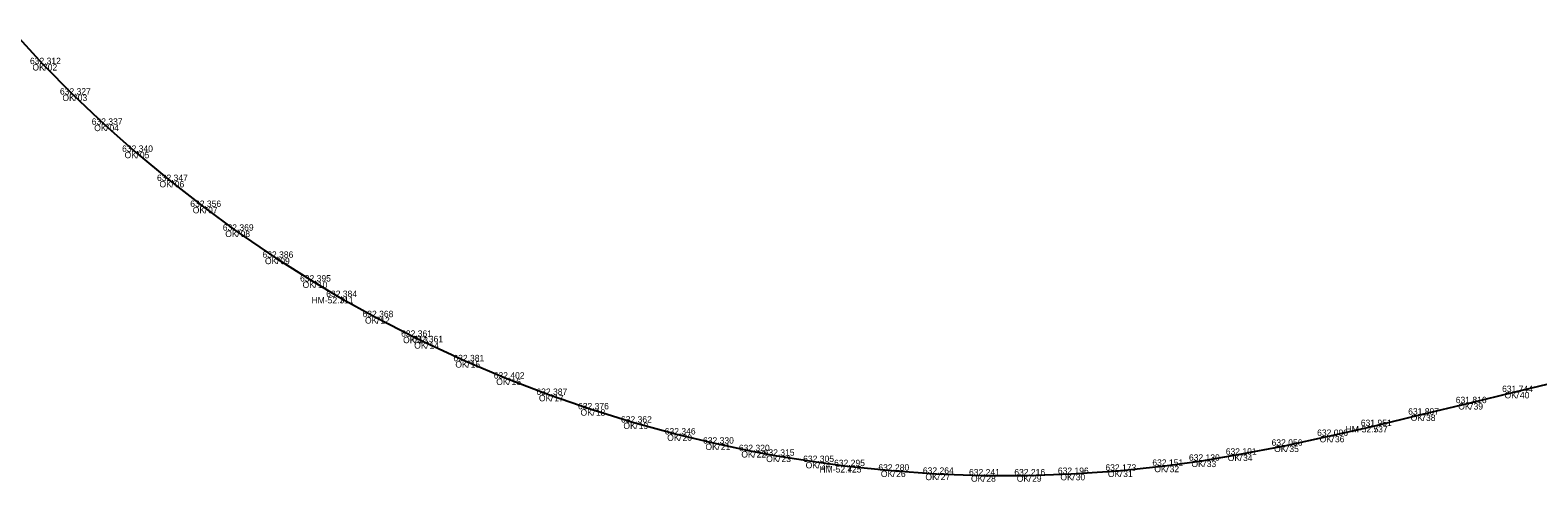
# Model space of a CAD drawing. Extents: x -631472 to -620808, y -1122356 to -1115125.
# Drawn here: x -627753.5 to -627470.2, y -1117415.3 to -1117330.3 of the extents above; entities that cross this region are included whole.
import ezdxf

# ---------------------------------------------------------------- set-up
doc = ezdxf.new("R2010")
doc.units = 0
for name, color, linetype in [('Vrstva 1', 7, 'Continuous'), ('Vrstva 60', 7, 'Continuous'), ('Vrstva 61', 7, 'Continuous'), ('Vrstva 62', 7, 'Continuous')]:
    doc.layers.add(name, color=color, linetype=linetype)

msp = doc.modelspace()

# ---------------------------------------------------------------- linework, layer by layer
at = {"layer": 'Vrstva 1'}
msp.add_lwpolyline([(-627757, -1117330.33), (-627751.12, -1117336.72), (-627745.48, -1117342.44), (-627739.51, -1117348.12), (-627733.8, -1117353.21), (-627727.24, -1117358.69), (-627720.98, -1117363.57), (-627714.88, -1117368.04), (-627707.42, -1117373.13), (-627700.35, -1117377.6), (-627695.44, -1117380.51), (-627688.62, -1117384.3), (-627681.45, -1117387.99), (-627679.37, -1117389.01), (-627671.64, -1117392.59), (-627663.96, -1117395.85), (-627655.94, -1117398.92), (-627648.11, -1117401.63), (-627640.05, -1117404.12), (-627631.82, -1117406.36), (-627624.63, -1117408.08), (-627617.9, -1117409.49), (-627613.23, -1117410.35), (-627605.81, -1117411.53), (-627599.99, -1117412.31), (-627591.68, -1117413.16), (-627583.31, -1117413.75), (-627574.73, -1117414.05), (-627566.13, -1117414.05), (-627557.94, -1117413.78), (-627549.01, -1117413.17), (-627540.29, -1117412.25), (-627533.31, -1117411.29), (-627526.48, -1117410.15), (-627517.78, -1117408.47), (-627509.22, -1117406.63), (-627501.1, -1117404.77), (-627492.1, -1117402.62), (-627483.17, -1117400.47), (-627474.46, -1117398.37), (-627466.85, -1117396.54)], dxfattribs=at)
at = {"layer": 'Vrstva 60'}
for p, q in [((-627751.12, -1117336.72), (-627751.12, -1117336.72)), ((-627745.48, -1117342.44), (-627745.48, -1117342.44)), ((-627739.51, -1117348.12), (-627739.51, -1117348.12)), ((-627733.8, -1117353.21), (-627733.8, -1117353.21)), ((-627727.24, -1117358.69), (-627727.24, -1117358.69)), ((-627720.98, -1117363.57), (-627720.98, -1117363.57)), ((-627714.88, -1117368.04), (-627714.88, -1117368.04)), ((-627707.42, -1117373.13), (-627707.42, -1117373.13)), ((-627700.35, -1117377.6), (-627700.35, -1117377.6)), ((-627695.44, -1117380.51), (-627695.44, -1117380.51)), ((-627688.62, -1117384.3), (-627688.62, -1117384.3)), ((-627681.45, -1117387.99), (-627681.45, -1117387.99)), ((-627679.37, -1117389.01), (-627679.37, -1117389.01)), ((-627671.64, -1117392.59), (-627671.64, -1117392.59)), ((-627663.96, -1117395.85), (-627663.96, -1117395.85)), ((-627474.46, -1117398.37), (-627474.46, -1117398.37)), ((-627655.94, -1117398.92), (-627655.94, -1117398.92)), ((-627483.17, -1117400.47), (-627483.17, -1117400.47)), ((-627648.11, -1117401.63), (-627648.11, -1117401.63)), ((-627640.05, -1117404.12), (-627640.05, -1117404.12)), ((-627492.1, -1117402.62), (-627492.1, -1117402.62)), ((-627631.82, -1117406.36), (-627631.82, -1117406.36)), ((-627509.22, -1117406.63), (-627509.22, -1117406.63)), ((-627501.1, -1117404.77), (-627501.1, -1117404.77)), ((-627624.63, -1117408.08), (-627624.63, -1117408.08)), ((-627617.9, -1117409.49), (-627617.9, -1117409.49)), ((-627517.78, -1117408.47), (-627517.78, -1117408.47)), ((-627613.23, -1117410.35), (-627613.23, -1117410.35)), ((-627605.81, -1117411.53), (-627605.81, -1117411.53)), ((-627599.99, -1117412.31), (-627599.99, -1117412.31)), ((-627540.29, -1117412.25), (-627540.29, -1117412.25)), ((-627533.31, -1117411.29), (-627533.31, -1117411.29)), ((-627526.48, -1117410.15), (-627526.48, -1117410.15)), ((-627591.68, -1117413.16), (-627591.68, -1117413.16)), ((-627583.31, -1117413.75), (-627583.31, -1117413.75)), ((-627574.73, -1117414.05), (-627574.73, -1117414.05)), ((-627566.13, -1117414.05), (-627566.13, -1117414.05)), ((-627557.94, -1117413.78), (-627557.94, -1117413.78)), ((-627549.01, -1117413.17), (-627549.01, -1117413.17))]:
    msp.add_line(p, q, dxfattribs=at)

# ---------------------------------------------------------------- texts
for s, p in [('702', (-627751.12, -1117337.92)), ('703', (-627745.48, -1117343.64)), ('704', (-627739.51, -1117349.32)), ('705', (-627733.8, -1117354.41)), ('706', (-627727.24, -1117359.89)), ('707', (-627720.98, -1117364.77)), ('708', (-627714.88, -1117369.24)), ('709', (-627707.42, -1117374.33)), ('710', (-627700.35, -1117378.8)), ('711', (-627695.44, -1117381.71)), ('712', (-627688.62, -1117385.5)), ('713', (-627681.45, -1117389.19)), ('714', (-627679.37, -1117390.21)), ('715', (-627671.64, -1117393.79)), ('716', (-627663.96, -1117397.05)), ('740', (-627474.46, -1117399.57)), ('717', (-627655.94, -1117400.12)), ('739', (-627483.17, -1117401.67)), ('718', (-627648.11, -1117402.83)), ('719', (-627640.05, -1117405.32)), ('738', (-627492.1, -1117403.82)), ('720', (-627631.82, -1117407.56)), ('736', (-627509.22, -1117407.83)), ('737', (-627501.1, -1117405.97)), ('721', (-627624.63, -1117409.28)), ('722', (-627617.9, -1117410.69)), ('735', (-627517.78, -1117409.67)), ('723', (-627613.23, -1117411.55)), ('724', (-627605.81, -1117412.74)), ('725', (-627599.99, -1117413.51)), ('732', (-627540.29, -1117413.45)), ('733', (-627533.31, -1117412.49)), ('734', (-627526.48, -1117411.35)), ('726', (-627591.68, -1117414.36)), ('727', (-627583.31, -1117414.95)), ('728', (-627574.73, -1117415.25)), ('729', (-627566.13, -1117415.25)), ('730', (-627557.94, -1117414.98)), ('731', (-627549.01, -1117414.37))]:
    msp.add_text(s, height=1.2, dxfattribs=at).set_placement(p)
at = {"layer": 'Vrstva 61'}
for s, p in [('632.312', (-627753.56, -1117336.72)), ('632.327', (-627747.93, -1117342.44)), ('632.337', (-627741.96, -1117348.12)), ('632.340', (-627736.25, -1117353.21)), ('632.347', (-627729.69, -1117358.69)), ('632.356', (-627723.44, -1117363.57)), ('632.369', (-627717.33, -1117368.04)), ('632.386', (-627709.87, -1117373.13)), ('632.395', (-627702.81, -1117377.6)), ('632.384', (-627697.89, -1117380.51)), ('632.368', (-627691.07, -1117384.3)), ('632.361', (-627683.81, -1117387.99)), ('632.361', (-627681.73, -1117389.01)), ('632.381', (-627673.99, -1117392.59)), ('632.402', (-627666.41, -1117395.85)), ('632.387', (-627658.39, -1117398.92)), ('631.744', (-627476.91, -1117398.37)), ('632.376', (-627650.57, -1117401.63)), ('631.897', (-627494.56, -1117402.62)), ('631.816', (-627485.62, -1117400.47)), ('632.362', (-627642.5, -1117404.12)), ('631.951', (-627503.46, -1117404.77)), ('632.346', (-627634.27, -1117406.36)), ('632.330', (-627627.08, -1117408.08)), ('632.006', (-627511.67, -1117406.63)), ('632.320', (-627620.35, -1117409.49)), ('632.315', (-627615.68, -1117410.35)), ('632.101', (-627528.84, -1117410.15)), ('632.056', (-627520.23, -1117408.47)), ('632.305', (-627608.26, -1117411.53)), ('632.295', (-627602.45, -1117412.31)), ('632.280', (-627594.13, -1117413.16)), ('632.264', (-627585.76, -1117413.75)), ('632.241', (-627577.09, -1117414.05)), ('632.216', (-627568.58, -1117414.05)), ('632.196', (-627560.39, -1117413.78)), ('632.173', (-627551.46, -1117413.17)), ('632.151', (-627542.64, -1117412.25)), ('632.130', (-627535.76, -1117411.29))]:
    msp.add_text(s, height=1.2, dxfattribs=at).set_placement(p)
at = {"layer": 'Vrstva 62'}
for s, p in [('OK', (-627753.1, -1117337.92)), ('OK', (-627747.46, -1117343.64)), ('OK', (-627741.49, -1117349.32)), ('OK', (-627735.78, -1117354.41)), ('OK', (-627729.22, -1117359.89)), ('OK', (-627722.97, -1117364.77)), ('OK', (-627716.86, -1117369.24)), ('OK', (-627709.4, -1117374.33)), ('OK', (-627702.33, -1117378.8)), ('HM-52.3', (-627700.65, -1117381.71)), ('OK', (-627690.6, -1117385.5)), ('OK', (-627683.44, -1117389.19)), ('OK', (-627681.35, -1117390.21)), ('OK', (-627673.62, -1117393.79)), ('OK', (-627665.94, -1117397.05)), ('OK', (-627476.45, -1117399.57)), ('OK', (-627657.92, -1117400.12)), ('OK', (-627485.15, -1117401.67)), ('OK', (-627650.1, -1117402.83)), ('OK', (-627642.04, -1117405.32)), ('OK', (-627494.09, -1117403.82)), ('OK', (-627633.81, -1117407.56)), ('OK', (-627511.2, -1117407.83)), ('HM-52.5', (-627506.32, -1117405.97)), ('OK', (-627626.62, -1117409.28)), ('OK', (-627619.88, -1117410.69)), ('OK', (-627519.76, -1117409.67)), ('OK', (-627615.21, -1117411.55)), ('OK', (-627607.79, -1117412.74)), ('HM-52.4', (-627605.19, -1117413.51)), ('OK', (-627542.27, -1117413.45)), ('OK', (-627535.29, -1117412.49)), ('OK', (-627528.47, -1117411.35)), ('OK', (-627593.66, -1117414.36)), ('OK', (-627585.29, -1117414.95)), ('OK', (-627576.72, -1117415.25)), ('OK', (-627568.11, -1117415.25)), ('OK', (-627559.92, -1117414.98)), ('OK', (-627550.99, -1117414.37))]:
    msp.add_text(s, height=1.2, dxfattribs=at).set_placement(p)

doc.saveas('drawing.dxf')
